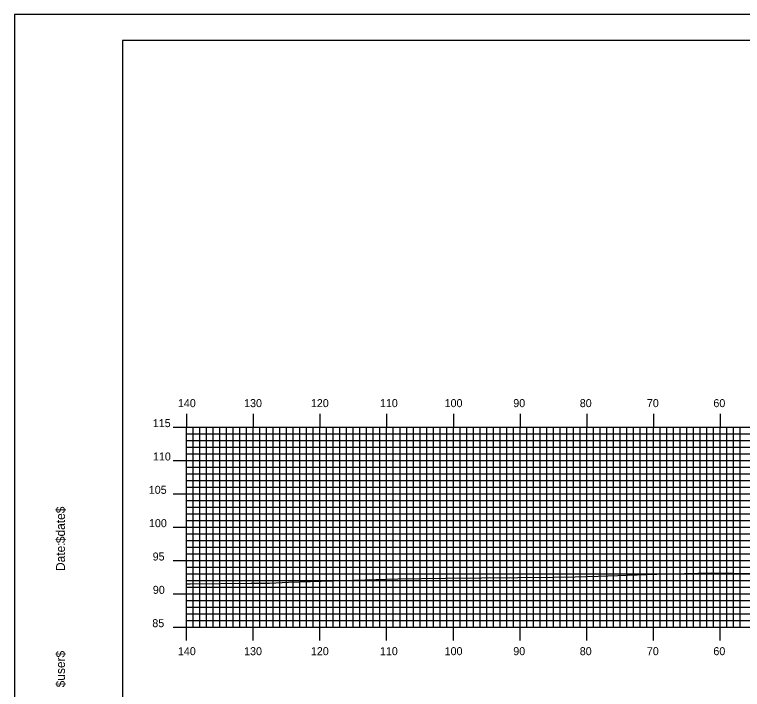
# Model space of a CAD drawing. Extents: x 1760610 to 1760954, y 442591 to 442811.
# Drawn here: x 1760610.4 to 1760719.5, y 442709.3 to 442810.5 of the extents above; entities that cross this region are included whole.
import ezdxf

# ---------------------------------------------------------------- set-up
doc = ezdxf.new("R2010")
doc.units = 0
for name, color, linetype in [('BORDER', 7, 'Continuous'), ('H_V ANNOTATION', 7, 'Continuous'), ('MAJOR', 7, 'Continuous'), ('MINOR', 7, 'Continuous'), ('PLOT BOUNDARY', 7, 'Continuous'), ('S_Roadway_Centerline', 7, 'Continuous')]:
    doc.layers.add(name, color=color, linetype=linetype)

msp = doc.modelspace()

# ---------------------------------------------------------------- linework, layer by layer
at = {"layer": 'BORDER'}
msp.add_lwpolyline([(1760626.61, 442596.67), (1760946.61, 442596.67), (1760946.61, 442806.67), (1760626.61, 442806.67)], close=True, dxfattribs=at)
at = {"layer": 'MAJOR'}
for p, q in [((1760636.21, 442750.67), (1760636.21, 442748.67)), ((1760646.21, 442750.67), (1760646.21, 442748.67)), ((1760656.21, 442750.67), (1760656.21, 442748.67)), ((1760666.21, 442750.67), (1760666.21, 442748.67)), ((1760676.21, 442750.67), (1760676.21, 442748.67)), ((1760686.21, 442750.67), (1760686.21, 442748.67)), ((1760696.21, 442750.67), (1760696.21, 442748.67)), ((1760706.21, 442750.67), (1760706.21, 442748.67)), ((1760716.21, 442750.67), (1760716.21, 442748.67)), ((1760634.21, 442748.67), (1760636.21, 442748.67)), ((1760636.21, 442748.67), (1760916.21, 442748.67)), ((1760636.21, 442718.67), (1760636.21, 442748.67)), ((1760636.21, 442718.67), (1760636.21, 442748.67)), ((1760636.21, 442748.67), (1760916.21, 442748.67)), ((1760646.21, 442718.67), (1760646.21, 442748.67)), ((1760656.21, 442718.67), (1760656.21, 442748.67)), ((1760666.21, 442718.67), (1760666.21, 442748.67)), ((1760676.21, 442718.67), (1760676.21, 442748.67)), ((1760686.21, 442718.67), (1760686.21, 442748.67)), ((1760696.21, 442718.67), (1760696.21, 442748.67)), ((1760706.21, 442718.67), (1760706.21, 442748.67)), ((1760716.21, 442718.67), (1760716.21, 442748.67)), ((1760634.21, 442743.67), (1760636.21, 442743.67)), ((1760636.21, 442743.67), (1760916.21, 442743.67)), ((1760634.21, 442738.67), (1760636.21, 442738.67)), ((1760636.21, 442738.67), (1760916.21, 442738.67)), ((1760634.21, 442733.67), (1760636.21, 442733.67)), ((1760636.21, 442733.67), (1760916.21, 442733.67)), ((1760634.21, 442728.67), (1760636.21, 442728.67)), ((1760636.21, 442728.67), (1760916.21, 442728.67)), ((1760634.21, 442723.67), (1760636.21, 442723.67)), ((1760636.21, 442723.67), (1760916.21, 442723.67)), ((1760634.21, 442718.67), (1760636.21, 442718.67)), ((1760636.21, 442718.67), (1760916.21, 442718.67)), ((1760636.21, 442718.67), (1760916.21, 442718.67)), ((1760636.21, 442716.66), (1760636.21, 442718.67)), ((1760646.21, 442716.66), (1760646.21, 442718.67)), ((1760656.21, 442716.66), (1760656.21, 442718.67)), ((1760666.21, 442716.66), (1760666.21, 442718.67)), ((1760676.21, 442716.66), (1760676.21, 442718.67)), ((1760686.21, 442716.66), (1760686.21, 442718.67)), ((1760696.21, 442716.66), (1760696.21, 442718.67)), ((1760706.21, 442716.66), (1760706.21, 442718.67)), ((1760716.21, 442716.66), (1760716.21, 442718.67))]:
    msp.add_line(p, q, dxfattribs=at)
at = {"layer": 'MINOR'}
for p, q in [((1760637.21, 442718.67), (1760637.21, 442748.67)), ((1760638.21, 442718.67), (1760638.21, 442748.67)), ((1760639.21, 442718.67), (1760639.21, 442748.67)), ((1760640.21, 442718.67), (1760640.21, 442748.67)), ((1760641.21, 442718.67), (1760641.21, 442748.67)), ((1760642.21, 442718.67), (1760642.21, 442748.67)), ((1760643.21, 442718.67), (1760643.21, 442748.67)), ((1760644.21, 442718.67), (1760644.21, 442748.67)), ((1760645.21, 442718.67), (1760645.21, 442748.67)), ((1760647.21, 442718.67), (1760647.21, 442748.67)), ((1760648.21, 442718.67), (1760648.21, 442748.67)), ((1760649.21, 442718.67), (1760649.21, 442748.67)), ((1760650.21, 442718.67), (1760650.21, 442748.67)), ((1760651.21, 442718.67), (1760651.21, 442748.67)), ((1760652.21, 442718.67), (1760652.21, 442748.67)), ((1760653.21, 442718.67), (1760653.21, 442748.67)), ((1760654.21, 442718.67), (1760654.21, 442748.67)), ((1760655.21, 442718.67), (1760655.21, 442748.67)), ((1760657.21, 442718.67), (1760657.21, 442748.67)), ((1760658.21, 442718.67), (1760658.21, 442748.67)), ((1760659.21, 442718.67), (1760659.21, 442748.67)), ((1760660.21, 442718.67), (1760660.21, 442748.67)), ((1760661.21, 442718.67), (1760661.21, 442748.67)), ((1760662.21, 442718.67), (1760662.21, 442748.67)), ((1760663.21, 442718.67), (1760663.21, 442748.67)), ((1760664.21, 442718.67), (1760664.21, 442748.67)), ((1760665.21, 442718.67), (1760665.21, 442748.67)), ((1760667.21, 442718.67), (1760667.21, 442748.67)), ((1760668.21, 442718.67), (1760668.21, 442748.67)), ((1760669.21, 442718.67), (1760669.21, 442748.67)), ((1760670.21, 442718.67), (1760670.21, 442748.67)), ((1760671.21, 442718.67), (1760671.21, 442748.67)), ((1760672.21, 442718.67), (1760672.21, 442748.67)), ((1760673.21, 442718.67), (1760673.21, 442748.67)), ((1760674.21, 442718.67), (1760674.21, 442748.67)), ((1760675.21, 442718.67), (1760675.21, 442748.67)), ((1760677.21, 442718.67), (1760677.21, 442748.67)), ((1760678.21, 442718.67), (1760678.21, 442748.67)), ((1760679.21, 442718.67), (1760679.21, 442748.67)), ((1760680.21, 442718.67), (1760680.21, 442748.67)), ((1760681.21, 442718.67), (1760681.21, 442748.67)), ((1760682.21, 442718.67), (1760682.21, 442748.67)), ((1760683.21, 442718.67), (1760683.21, 442748.67)), ((1760684.21, 442718.67), (1760684.21, 442748.67)), ((1760685.21, 442718.67), (1760685.21, 442748.67)), ((1760687.21, 442718.67), (1760687.21, 442748.67)), ((1760688.21, 442718.67), (1760688.21, 442748.67)), ((1760689.21, 442718.67), (1760689.21, 442748.67)), ((1760690.21, 442718.67), (1760690.21, 442748.67)), ((1760691.21, 442718.67), (1760691.21, 442748.67)), ((1760692.21, 442718.67), (1760692.21, 442748.67)), ((1760693.21, 442718.67), (1760693.21, 442748.67)), ((1760694.21, 442718.67), (1760694.21, 442748.67)), ((1760695.21, 442718.67), (1760695.21, 442748.67)), ((1760697.21, 442718.67), (1760697.21, 442748.67)), ((1760698.21, 442718.67), (1760698.21, 442748.67)), ((1760699.21, 442718.67), (1760699.21, 442748.67)), ((1760700.21, 442718.67), (1760700.21, 442748.67)), ((1760701.21, 442718.67), (1760701.21, 442748.67)), ((1760702.21, 442718.67), (1760702.21, 442748.67)), ((1760703.21, 442718.67), (1760703.21, 442748.67)), ((1760704.21, 442718.67), (1760704.21, 442748.67)), ((1760705.21, 442718.67), (1760705.21, 442748.67)), ((1760707.21, 442718.67), (1760707.21, 442748.67)), ((1760708.21, 442718.67), (1760708.21, 442748.67)), ((1760709.21, 442718.67), (1760709.21, 442748.67)), ((1760710.21, 442718.67), (1760710.21, 442748.67)), ((1760711.21, 442718.67), (1760711.21, 442748.67)), ((1760712.21, 442718.67), (1760712.21, 442748.67)), ((1760713.21, 442718.67), (1760713.21, 442748.67)), ((1760714.21, 442718.67), (1760714.21, 442748.67)), ((1760715.21, 442718.67), (1760715.21, 442748.67)), ((1760717.21, 442718.67), (1760717.21, 442748.67)), ((1760718.21, 442718.67), (1760718.21, 442748.67)), ((1760719.21, 442718.67), (1760719.21, 442748.67)), ((1760636.21, 442747.67), (1760916.21, 442747.67)), ((1760636.21, 442747.67), (1760638.22, 442747.67)), ((1760636.21, 442746.67), (1760916.21, 442746.67)), ((1760636.21, 442746.67), (1760638.22, 442746.67)), ((1760636.21, 442745.67), (1760916.21, 442745.67)), ((1760636.21, 442745.67), (1760638.22, 442745.67)), ((1760636.21, 442744.67), (1760916.21, 442744.67)), ((1760636.21, 442744.67), (1760638.22, 442744.67)), ((1760636.21, 442742.67), (1760916.21, 442742.67)), ((1760636.21, 442742.67), (1760638.22, 442742.67)), ((1760636.21, 442741.67), (1760916.21, 442741.67)), ((1760636.21, 442741.67), (1760638.22, 442741.67)), ((1760636.21, 442740.67), (1760916.21, 442740.67)), ((1760636.21, 442740.67), (1760638.22, 442740.67)), ((1760636.21, 442739.67), (1760916.21, 442739.67)), ((1760636.21, 442739.67), (1760638.22, 442739.67)), ((1760636.21, 442737.67), (1760916.21, 442737.67)), ((1760636.21, 442737.67), (1760638.22, 442737.67)), ((1760636.21, 442736.67), (1760916.21, 442736.67)), ((1760636.21, 442736.67), (1760638.22, 442736.67)), ((1760636.21, 442735.67), (1760916.21, 442735.67)), ((1760636.21, 442735.67), (1760638.22, 442735.67)), ((1760636.21, 442734.67), (1760916.21, 442734.67)), ((1760636.21, 442734.67), (1760638.22, 442734.67)), ((1760636.21, 442732.67), (1760916.21, 442732.67)), ((1760636.21, 442732.67), (1760638.22, 442732.67)), ((1760636.21, 442731.67), (1760916.21, 442731.67)), ((1760636.21, 442731.67), (1760638.22, 442731.67)), ((1760636.21, 442730.67), (1760916.21, 442730.67)), ((1760636.21, 442730.67), (1760638.22, 442730.67)), ((1760636.21, 442729.67), (1760916.21, 442729.67)), ((1760636.21, 442729.67), (1760638.22, 442729.67)), ((1760636.21, 442727.67), (1760916.21, 442727.67)), ((1760636.21, 442727.67), (1760638.22, 442727.67)), ((1760636.21, 442726.67), (1760916.21, 442726.67)), ((1760636.21, 442726.67), (1760638.22, 442726.67)), ((1760636.21, 442725.67), (1760916.21, 442725.67)), ((1760636.21, 442725.67), (1760638.22, 442725.67)), ((1760636.21, 442724.67), (1760916.21, 442724.67)), ((1760636.21, 442724.67), (1760638.22, 442724.67)), ((1760636.21, 442722.67), (1760916.21, 442722.67)), ((1760636.21, 442722.67), (1760638.22, 442722.67)), ((1760636.21, 442721.67), (1760916.21, 442721.67)), ((1760636.21, 442721.67), (1760638.22, 442721.67)), ((1760636.21, 442720.67), (1760916.21, 442720.67)), ((1760636.21, 442720.67), (1760638.22, 442720.67)), ((1760636.21, 442719.67), (1760916.21, 442719.67)), ((1760636.21, 442719.67), (1760638.22, 442719.67))]:
    msp.add_line(p, q, dxfattribs=at)
at = {"layer": 'PLOT BOUNDARY'}
msp.add_lwpolyline([(1760610.43, 442590.55), (1760950.43, 442590.55), (1760950.43, 442810.55), (1760610.43, 442810.55)], close=True, dxfattribs=at)
at = {"layer": 'S_Roadway_Centerline'}
msp.add_lwpolyline([(1760636.21, 442725.18), (1760636.74, 442725.19), (1760645.91, 442725.28), (1760648.67, 442725.29), (1760651.5, 442725.43), (1760667.9, 442725.92), (1760675.05, 442726.04), (1760691.29, 442726.15), (1760694.48, 442726.22), (1760697.91, 442726.31), (1760706.72, 442726.6), (1760714.94, 442726.8), (1760721.21, 442726.74)], dxfattribs=at)

# ---------------------------------------------------------------- texts
at = {"layer": 'BORDER'}
for s, p in [('$date$', (1760617.98, 442731.28)), ('Date:', (1760617.98, 442727.1)), ('$user$', (1760617.98, 442709.65))]:
    msp.add_text(s, height=1.339, rotation=90, dxfattribs=at).set_placement(p)
at = {"layer": 'H_V ANNOTATION'}
for s, p in [('140', (1760634.92, 442751.67)), ('130', (1760644.84, 442751.67)), ('120', (1760654.85, 442751.67)), ('110', (1760665.2, 442751.67)), ('100', (1760674.9, 442751.67)), ('90', (1760685.19, 442751.67)), ('80', (1760695.16, 442751.67)), ('70', (1760705.22, 442751.67)), ('60', (1760715.19, 442751.67)), ('115', (1760631.15, 442748.67)), ('110', (1760631.18, 442743.67)), ('105', (1760630.55, 442738.67)), ('100', (1760630.58, 442733.67)), ('95', (1760631.13, 442728.67)), ('90', (1760631.16, 442723.67)), ('85', (1760631.08, 442718.67)), ('140', (1760634.92, 442714.47)), ('130', (1760644.84, 442714.47)), ('120', (1760654.85, 442714.47)), ('110', (1760665.2, 442714.47)), ('100', (1760674.9, 442714.47)), ('90', (1760685.19, 442714.47)), ('80', (1760695.16, 442714.47)), ('70', (1760705.22, 442714.47)), ('60', (1760715.19, 442714.47))]:
    msp.add_text(s, height=1.2, dxfattribs=at).set_placement(p)
at = {"layer": 'MAJOR'}
msp.add_text('-', height=0.012, dxfattribs=at).set_placement((1760636.2, 442718.67))

doc.saveas('drawing.dxf')
